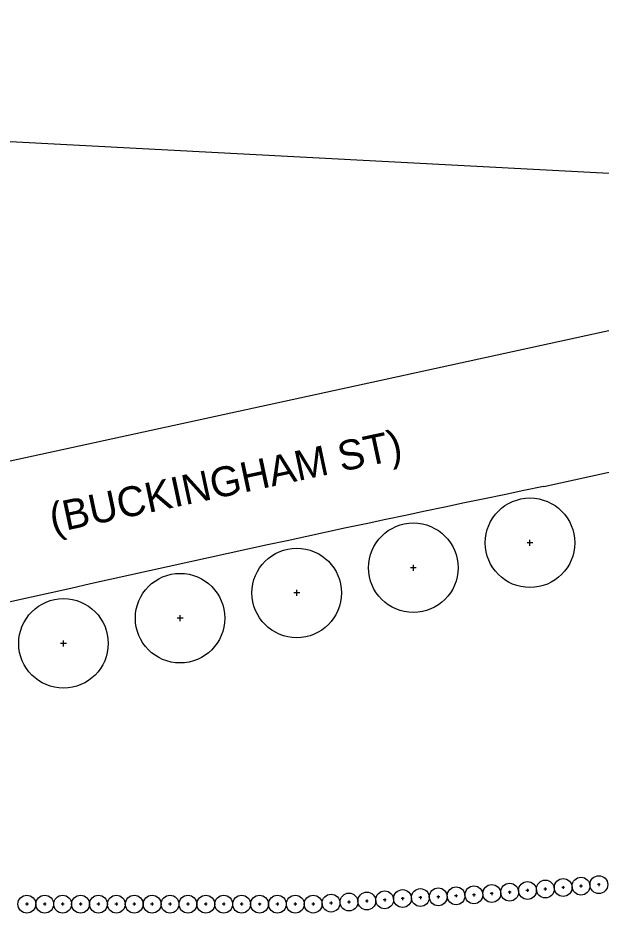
# Model space of a CAD drawing. Extents: x -9648 to 41057, y -12373 to 40276.
# Drawn here: x 7918.6 to 8114.2, y 1650.9 to 1950.9 of the extents above; entities that cross this region are included whole.
import ezdxf

# ---------------------------------------------------------------- set-up
doc = ezdxf.new("R2010")
doc.units = 0
for name, color, linetype in [('Default', 7, 'Continuous'), ('SC_Scratch1', 7, 'Continuous'), ('SH_Data', 7, 'Continuous'), ('VG_P_Cells', 7, 'Continuous')]:
    doc.layers.add(name, color=color, linetype=linetype)

# ---------------------------------------------------------------- blocks, each defined once
blk = doc.blocks.new('30_Dec')
at = {"layer": 'VG_P_Cells'}
for p, q in [((0.999998, 0), (-0.999998, 0)), ((0, -0.999998), (0, 0.999998))]:
    blk.add_line(p, q, dxfattribs=at)
blk.add_circle((0, 0), 14.99997, dxfattribs=at)

msp = doc.modelspace()

# ---------------------------------------------------------------- linework, layer by layer
at = {"layer": 'SC_Scratch1'}
msp.add_line((7131.91, 1950.91), (9388.76, 1831.69), dxfattribs=at)
at = {"layer": 'SH_Data'}
for points in [[(8334.08, 1893.23), (8186.99, 1861.32), (8039.92, 1829.27), (7775.75, 1771.92)], [(8094.94, 1793.9), (8225.66, 1822.55), (8192.01, 1815.18)]]:
    msp.add_lwpolyline(points, dxfattribs=at)
msp.add_arc((10055.47, -7699.17), 9693.4, 101.669183, 102.947183, dxfattribs=at)
at = {"layer": 'VG_P_Cells'}
for p, q in [((8089.49, 1659.03), (8089.49, 1658.03)), ((8095.97, 1659.01), (8094.97, 1659.01)), ((8095.47, 1659.51), (8095.47, 1658.51)), ((8101.95, 1659.52), (8100.95, 1659.52)), ((8101.45, 1660.02), (8101.45, 1659.02)), ((8107.93, 1659.98), (8106.93, 1659.98)), ((8107.43, 1660.48), (8107.43, 1659.48)), ((8113.91, 1660.49), (8112.91, 1660.49)), ((8113.41, 1660.99), (8113.41, 1660)), ((8041.61, 1655.87), (8041.61, 1654.87)), ((8047.6, 1656.3), (8047.6, 1655.31)), ((8054.08, 1656.14), (8053.08, 1656.14)), ((8053.58, 1656.64), (8053.58, 1655.64)), ((8060.07, 1656.39), (8059.07, 1656.39)), ((8059.57, 1656.89), (8059.57, 1655.89)), ((8066.05, 1656.72), (8065.05, 1656.72)), ((8065.55, 1657.22), (8065.55, 1656.23)), ((8072.03, 1657.06), (8071.04, 1657.06)), ((8071.53, 1657.56), (8071.53, 1656.56)), ((8078.02, 1657.5), (8077.02, 1657.5)), ((8077.52, 1658), (8077.52, 1657)), ((8084, 1657.94), (8083, 1657.94)), ((8083.5, 1658.43), (8083.5, 1657.44)), ((8089.99, 1658.53), (8088.99, 1658.53)), ((7922.15, 1653.95), (7921.15, 1653.95)), ((7921.65, 1654.45), (7921.65, 1653.45)), ((7928.15, 1653.95), (7927.15, 1653.95)), ((7927.65, 1654.45), (7927.65, 1653.45)), ((7934.15, 1653.95), (7933.15, 1653.95)), ((7933.65, 1654.45), (7933.65, 1653.45)), ((7940.15, 1653.95), (7939.15, 1653.95)), ((7939.65, 1654.45), (7939.65, 1653.45)), ((7946.15, 1653.95), (7945.15, 1653.95)), ((7945.65, 1654.44), (7945.65, 1653.45)), ((7952.15, 1653.94), (7951.15, 1653.94)), ((7951.65, 1654.44), (7951.65, 1653.45)), ((7958.15, 1653.94), (7957.15, 1653.94)), ((7957.65, 1654.44), (7957.65, 1653.44)), ((7964.15, 1653.94), (7963.15, 1653.94)), ((7963.65, 1654.44), (7963.65, 1653.44)), ((7970.15, 1653.94), (7969.15, 1653.94)), ((7969.65, 1654.44), (7969.65, 1653.44)), ((7976.15, 1653.94), (7975.15, 1653.94)), ((7975.65, 1654.44), (7975.65, 1653.44)), ((7982.15, 1653.94), (7981.15, 1653.94)), ((7981.65, 1654.44), (7981.65, 1653.44)), ((7988.15, 1653.94), (7987.15, 1653.94)), ((7987.65, 1654.44), (7987.65, 1653.44)), ((7994.15, 1653.94), (7993.15, 1653.94)), ((7993.65, 1654.44), (7993.65, 1653.44)), ((8000.15, 1653.94), (7999.15, 1653.94)), ((7999.65, 1654.43), (7999.65, 1653.44)), ((8006.15, 1653.94), (8005.15, 1653.94)), ((8005.65, 1654.44), (8005.65, 1653.44)), ((8012.15, 1653.95), (8011.15, 1653.95)), ((8011.65, 1654.45), (8011.65, 1653.45)), ((8018.15, 1653.96), (8017.15, 1653.96)), ((8017.65, 1654.45), (8017.65, 1653.46)), ((8024.13, 1654.3), (8023.13, 1654.3)), ((8023.63, 1654.8), (8023.63, 1653.8)), ((8030.15, 1654.64), (8029.15, 1654.64)), ((8029.65, 1655.14), (8029.65, 1654.14)), ((8036.13, 1654.99), (8035.13, 1654.99)), ((8035.63, 1655.49), (8035.63, 1654.49)), ((8042.11, 1655.37), (8041.12, 1655.37)), ((8048.1, 1655.81), (8047.1, 1655.81))]:
    msp.add_line(p, q, dxfattribs=at)
for centre in [(8095.47, 1659.01), (8101.45, 1659.52), (8107.43, 1659.98), (8113.41, 1660.49), (8053.58, 1656.14), (8059.57, 1656.39), (8065.55, 1656.72), (8071.53, 1657.06), (8077.52, 1657.5), (8083.5, 1657.94), (8089.49, 1658.53), (7921.65, 1653.95), (7927.65, 1653.95), (7933.65, 1653.95), (7939.65, 1653.95), (7945.65, 1653.95), (7951.65, 1653.94), (7957.65, 1653.94), (7963.65, 1653.94), (7969.65, 1653.94), (7975.65, 1653.94), (7981.65, 1653.94), (7987.65, 1653.94), (7993.65, 1653.94), (7999.65, 1653.94), (8005.65, 1653.94), (8011.65, 1653.95), (8017.65, 1653.96), (8023.63, 1654.3), (8029.65, 1654.64), (8035.63, 1654.99), (8041.61, 1655.37), (8047.6, 1655.81)]:
    msp.add_circle(centre, 2.99, dxfattribs=at)

# ---------------------------------------------------------------- block references
at = {"layer": 'Default'}
for p in [(8090.33, 1775.04), (8051.22, 1766.68), (8012.12, 1758.22), (7973.02, 1749.77), (7933.93, 1741.32)]:
    msp.add_blockref('30_Dec', p, dxfattribs=at)

# ---------------------------------------------------------------- texts
at = {"layer": 'SC_Scratch1'}
msp.add_text('(BUCKINGHAM ST)', height=10, rotation=12.0382, dxfattribs=at).set_placement((7930.41, 1778.2))

doc.saveas('drawing.dxf')
